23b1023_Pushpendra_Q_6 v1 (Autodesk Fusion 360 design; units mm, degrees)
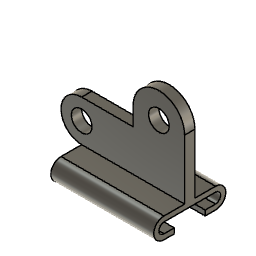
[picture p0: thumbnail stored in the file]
sketch "Sketch1" plane through (0, 0, 0) normal (0, 1, 0) x axis (1, 0, 0)
  line L1 (50, -25) -> (-50, -25)
  line L2 (0, -65) -> (-50, -65)
  line L3 (0, -83) -> (0, -65)
  line L4 (50, -83) -> (50, -25)
  arc A1 centre (-50, -45) radius 20 clockwise from (-50, -65) to (-50, -25)
  arc A2 centre (25, -83) radius 25 clockwise from (50, -83) to (0, -83)
  circle C1 centre (25, -83) radius 10
  circle C2 centre (-50, -45) radius 10
  point P1 (0, 0)
  point P10 (25, -83)
  point P6 (-50, -45)
  horizontal L1
  tangent L1 A1
  tangent L2 A1
  perpendicular L2 L3
  perpendicular L1 L4
  tangent L3 A2
  tangent L4 A2
  concentric A2 C1
  concentric A1 C2
  dimension "d1" radius A1 = 20
  dimension "d4" radius A2 = 25
  dimension "d5" diameter C1 = 20
  dimension "d6" diameter C2 = 20
  dimension "d7" distance P1 L1 = 25
  dimension "d8" distance P1 L4 = 50
  dimension "d9" distance P1 L2 = 65
  dimension "d10" distance P1 P10 = 83
  dimension "d11" distance P1 P6 = 67.2681
extrude "Extrude1" new body sketch "Sketch1" along normal blind 10
sketch "Sketch2" plane through (50, 0, 0) normal (1, 0, 0) x axis (0, 1, 0)
  line L1 (0, 25) -> (0, 83)
  line L2 (10, 25) -> (0, 25)
  line L3 (10, 83) -> (10, 25)
  line L4 (0, 83) -> (10, 83)
  line L5 (30, 25) -> (10, 25)
  line L6 (-20, 25) -> (0, 25)
  line L7 (30, 20) -> (-20, 20)
  line L8 (20, 10) -> (30, 10)
  line L9 (30, 5) -> (20, 5)
  line L10 (-10, 10) -> (-20, 10)
  line L11 (-10, 5) -> (-20, 5)
  line L12 (-10, 5) -> (-10, 10)
  line L13 (20, 5) -> (20, 10)
  arc A1 centre (-20, 15) radius 10 clockwise from (-20, 5) to (-20, 25)
  arc A2 centre (-20, 15) radius 5 clockwise from (-20, 10) to (-20, 20)
  arc A3 centre (30, 15) radius 10 clockwise from (30, 25) to (30, 5)
  arc A4 centre (30, 15) radius 5 clockwise from (30, 20) to (30, 10)
  point P4 (10, 25)
  point P6 (10, 25)
  point P3 (0, 25)
  point P7 (0, 25)
  point P1 (0, 0)
  point P20 (30, 15)
  point P23 (30, 15)
  point P14 (-20, 15)
  point P17 (-20, 15)
  coincident P4 P6
  perpendicular L3 L5
  coincident P3 P7
  perpendicular L1 L6
  horizontal L7
  horizontal L8
  parallel L8 L9
  horizontal L10
  horizontal L11
  tangent L6 A1
  tangent L11 A1
  tangent L7 A2
  tangent L10 A2
  perpendicular L11 L12
  perpendicular L9 L13
  tangent L9 A3
  tangent L5 A3
  tangent L7 A4
  tangent L8 A4
  dimension "d15" distance L5 L7 = 5
  dimension "d18" radius A1 L3 = 10
  dimension "d19" radius A2 = 5
  dimension "d20" radius A3 = 10
  dimension "d21" radius A4 = 5
  dimension "d22" distance P1 P20 = 33.541
  dimension "d23" distance P1 P23 = 33.541
  dimension "d24" distance P1 P14 = 25
  dimension "d25" distance P1 P17 = 25
  dimension "d26" distance P1 L13 = 20
  dimension "d27" distance P1 L12 = 10
extrude "Extrude2" add sketch "Sketch2" profile of L2 L5 L6 L7 L8 L9 L10 L11 A1 A2 L12 L13 A3 A4 against normal blind 100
